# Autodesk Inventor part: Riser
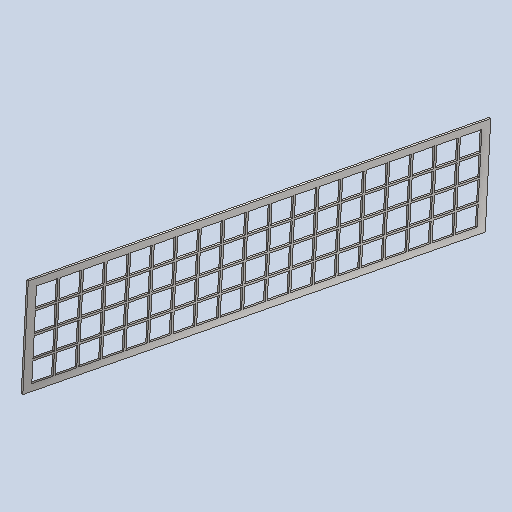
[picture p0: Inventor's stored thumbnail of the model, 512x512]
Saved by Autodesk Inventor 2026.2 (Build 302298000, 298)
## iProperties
RuleStatus: InUse
Created: 2022-06
Part Number: Riser
Material: Aluminum 6061
Document SubType Name: Modeling
Designer: reaumed
Density: 2.7 g/cm^3
Appearance: Aluminum - Flat
Mass: 1140.69 g
Surface Area: 2724.59 cm^2
Volume: 422.479 cm^3
AfterAnyParamChange0: pattern base location
AfterAnyUserParamChange0: pattern base location
Author: reaumed
Material: Steel, Galvanized
Density: 7.85 g/cm^3
Appearance: Galvanized
Mass: 845.798 g
Surface Area: 1112.5 cm^2
Volume: 107.745 cm^3
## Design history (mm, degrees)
workplane "Work Plane1"
sketch "Sketch1"
  geometry: L1 (-342.9, -222.25)-(342.9, -222.25); L2 (342.9, -222.25)-(342.9, -381); L3 (342.9, -381)-(-342.9, -381); L4 (-342.9, -381)-(-342.9, -222.25); 3 further points
  constraints: 8 end point, 2 parallel, 1 coincident, 1 horizontal, 1 midpoint, 1 perpendicular
  dimensions: "ActualRiserWidth" = 685.8 distance of L2.end L3.end (= Width - 2 x StringerThickness); "ActualRiserHeight" = 158.75 distance of L1.end L2.end (= Rise - TreadThickness); "d5" = 222.25 distance from line of L1 point (0, 0) (= Rise + TreadThickness); "d6" = 0 horizontal distance of point (0, 0) point (0, -222.25)
extrude "Extrusion1" new body sketch "Sketch1" distance "d3" = 3.175 (= RiserThickness); taper "d4" = 0 deg
sketch "Sketch2"
  geometry: L1 (233.362, -330.2)-(265.112, -330.2); L2 (265.112, -330.2)-(265.112, -298.45); L3 (265.112, -298.45)-(233.362, -298.45); L4 (233.362, -298.45)-(233.362, -330.2); L5 (233.362, -330.2)-(265.112, -298.45); L6 (381, -342.9)-(381, 342.9) reference; L7 (381, 342.9)-(222.25, 342.9) reference; L8 (381, -342.9)-(222.25, 342.9); 3 further points
  constraints: 12 end point, 2 midpoint, 2 parallel, 1 horizontal, 1 perpendicular
  dimensions: "d7" = 31.75 distance of L2.end L3.end (= HoleSize); "HoleSize" = 31.75 distance of L3.end L1.start; "x_loc" = 314.325 vertical distance of point (249.237, -314.325) point (0, 0); "y_loc" = 52.3875 horizontal distance of point (301.625, 0) point (249.237, -314.325)
extrude "Grating Extrusion" cut sketch "Sketch2" extent not by distance; stored distance "d12" = 0; taper "d13" = 0 deg
body "Solid1"
pattern_linear "Grating Pattern" dims "d16" = 34.925 (= HoleSize + HoleSpacing), "d19" = 34.925 (= HoleSize + HoleSpacing)
other parameters: "Run" = 228.6 [user parameter; used in 1 equation term], "Width" = 762 [user parameter; used in 1 equation term], "Rise" = 190.5 [user parameter; used in 2 equation terms], "TreadThickness" = 31.75 [user parameter; used in 2 equation terms], "RiserThickness" = 3.175 [user parameter; used in 1 equation term], "d0" = 228.6 (= Run), "StringerThickness" = 38.1 [user parameter; used in 1 equation term], "HoleSpacing" = 3.175 [user parameter; used in 2 equation terms]
